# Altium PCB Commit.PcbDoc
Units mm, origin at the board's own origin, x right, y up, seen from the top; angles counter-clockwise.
Board outline 42 x 80 mm, 2 copper layers (Top Layer, Bottom Layer); 82 components, 52 nets, 246 pads, 237 vias.
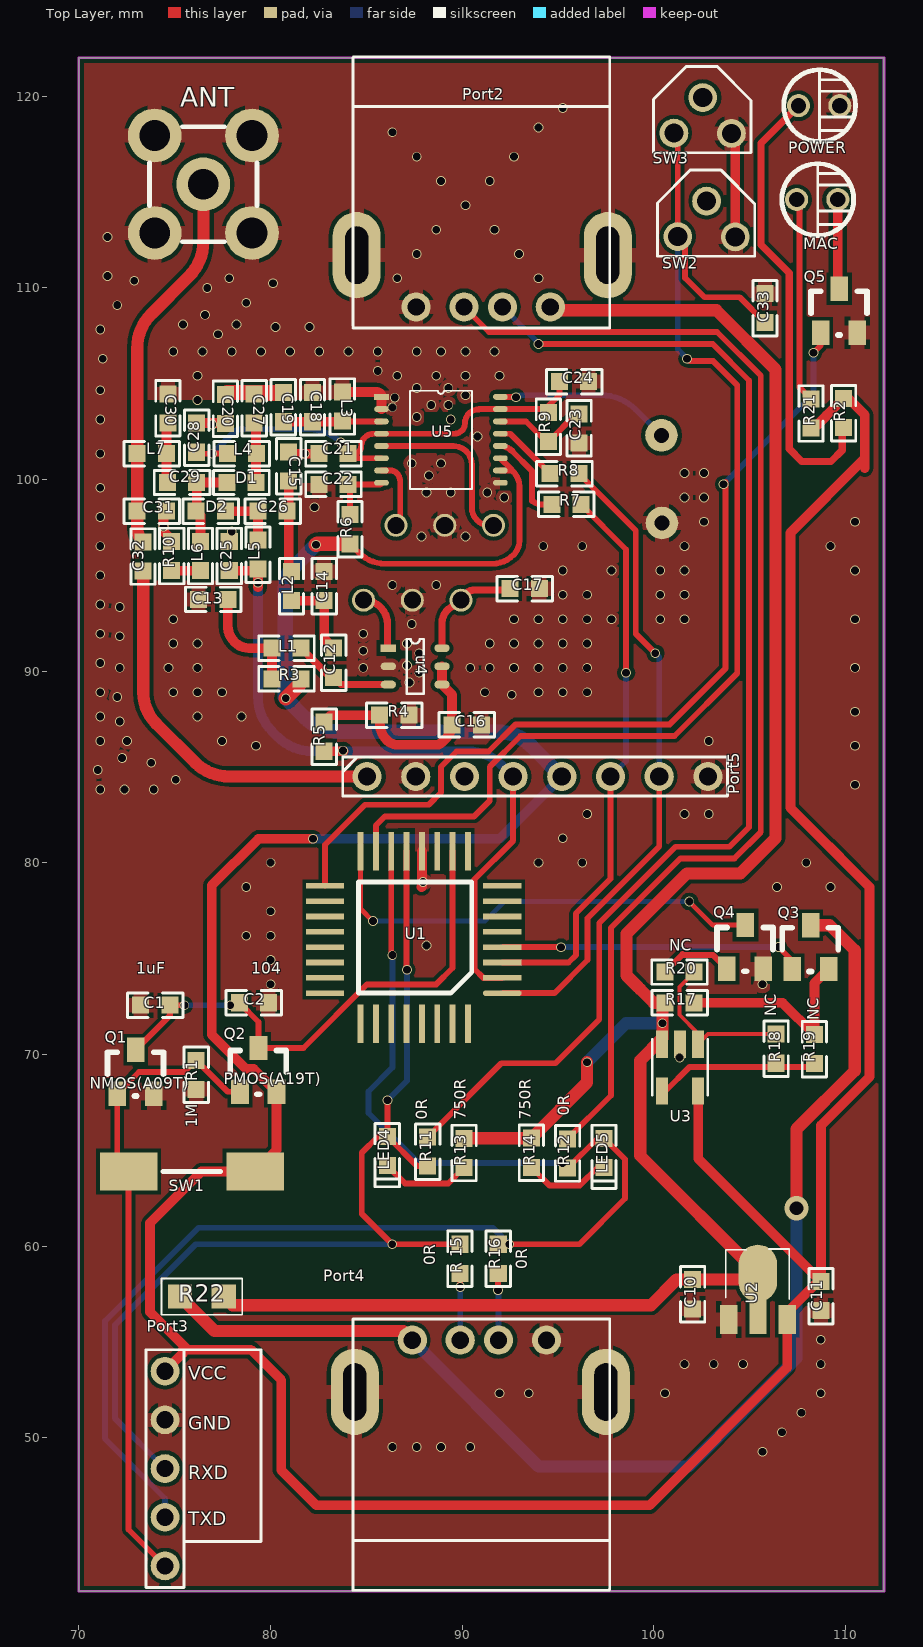
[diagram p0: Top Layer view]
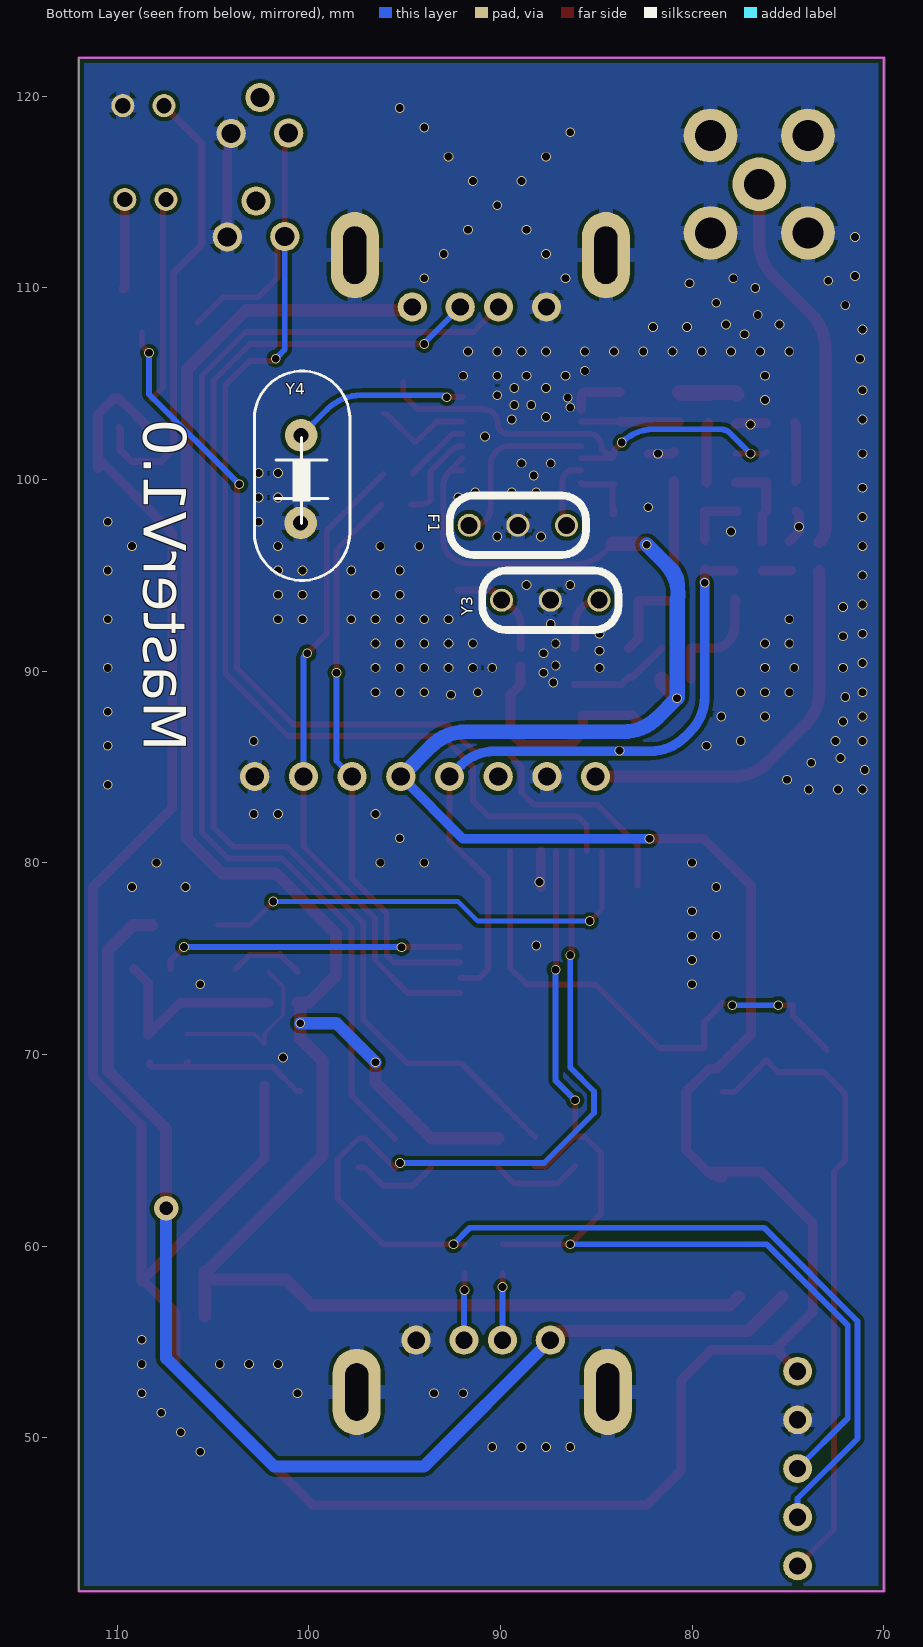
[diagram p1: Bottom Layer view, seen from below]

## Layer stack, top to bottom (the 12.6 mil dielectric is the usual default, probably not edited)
Top Layer: signal copper 0.0356
Dielectric: dielectric 0.32, FR-4, Dk 4.8
Bottom Layer: signal copper 0.0356

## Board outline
70,42 112,42 112,122 70,122

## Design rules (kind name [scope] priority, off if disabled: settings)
Clearance [All] p1: gap=0.203
ComponentClearance [All] p1: gap=0 collisioncheckmode=3 verticalgap=0 showdistances=FALSE
MinimumSolderMaskSliver [All] p1: minsoldermaskwidth=0
PolygonConnect [All] p1: connectstyle=Relief reliefconductorwidth=0.762 reliefentries=4 polygonreliefangle="90 Angle"
RoomDefinition CommitV2.0 [InComponentClass('CommitV2.0')] p1: confinementstyle=ConfineIn formatcopy=TRUE lockcomponents=FALSE outline 0,0 50.8,0 50.8,25.4 0,25.4
RoutingVias [All] p1: holewidth=1.27 width=2.54 viastyle="Through Hole" minholewidth=0.025 minwidth=0.254 maxholewidth=0.711 maxwidth=1.27
SilkToSilkClearance [All] p1: silktosilkclearance=0
SilkscreenOverComponentPads [All] p1: minsilkscreentomaskgap=0
SolderMaskExpansion [All] p1: expansion=0.102
Width [All] p1: maxlimit=0.762 minlimit=0.178 preferedwidth=0.381
24 further rules are at their usual default settings.

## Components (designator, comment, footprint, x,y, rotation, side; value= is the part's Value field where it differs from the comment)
ANT "SMA" SWA-KE天线母座 76.5,115.4 r0 top
C1 "1uF" 0603 73.228,72.572 r0 top
C2 "104" 0603 79.9,72.7 r180 top
C10 "1uF" 0603 102.022,58.258 r270 top
C11 "104" 0603 108.722,58.158 r270 top
C12 "220pF5%" 0603 83.3,91.2 r270 top
C13 "104" 0603 76.25,93.742 r0 top
C14 "4.7pF5%" 0603 82.8,95.2 r270 top
C15 "12pF5%" 0603 80.95,101.442 r270 top
C16 "104" 0603 91,87.2 r180 top
C17 "1pF+-0.25p" 0603 92.5,94.3 r0 top
C18 "NC" 0603 82.194,104.534 r270 top
C19 "1pF+-0.25p" 0603 80.67,104.534 r270 top
C20 "NC" 0603 77.65,104.442 r270 top
C21 "104" 0603 84.05,101.342 r180 top
C22 "104" 0603 84.05,99.742 r180 top
C23 "104" 0603 96.1,101.9 r90 top
C24 "104" 0603 96.6,105.1 r180 top
C25 "NC" 0603 77.85,95.242 r90 top
C26 "NC" 0603 79.35,98.342 r0 top
C27 "NC" 0603 79.15,102.942 r90 top
C28 "104" 0603 76.15,102.942 r270 top
C29 "220pF5%" 0603 76.15,99.842 r180 top
C30 "NC" 0603 74.65,102.942 r90 top
C31 "NC" 0603 73.05,98.342 r0 top
C32 "NC" 0603 73.35,96.742 r270 top
C33 "NC" 0603 105.8,109.7 r270 top
D1 "SMP1320" 0603 79.25,99.842 r180 top
D2 "SMP1320" 0603 77.65,98.342 r180 top
F1 "10.7M" "PT4450 XTAL" 89.093,97.607 r0 bottom
L1 "180nH5%" 0603 81.6,91.2 r180 top
L2 "22nH5%" 0603 81.1,95.2 r270 top
L3 "47nH5%" 0603 83.75,103.042 r90 top
L4 "180nH5%" 0603 77.75,101.342 r0 top
L5 "180nH5%" 0603 79.35,96.842 r270 top
L6 "180nH5%" 0603 76.35,95.242 r90 top
L7 "0R" 0603 73.05,101.342 r0 top
LED4 "RX" LED-0603 86.1,64.2 r90 top
LED5 "TX" LED-0603 97.4,64.1 r90 top
MAC "MAC" 2.54LED 109.8,114.6 r0 top
Port2 "USB_A" USB-A 91.1,109 r180 top
Port3 "DEBUG" STC_DEBUG 74.5,48.4 r0 top
Port4 "USB_B" USB-A 90.9,55.1 r0 top
Port5 "Mold" Pin-8 95.2,84.5 r90 top
POWER "POWER" 2.54LED 109.9,119.5 r0 top
Q1 "NMOS(A09T)" SOT-23 72.9,69.1 r0 top
Q2 "PMOS(A19T)" SOT-23 79.3,69.2 r0 top
Q3 "AO3407(P)" SOT-23 108.1,75.6 r0 top
Q4 "NC" SOT-23 104.7,75.61 r0 top
Q5 "NMOS(A09T)" SOT-23 109.6,108.8 r0 top
R1 "1M" 0603 76.128,68.172 r90 top
R2 "2.2K" 0603 109.9,102.7 r90 top
R3 "0R" 0603 81.6,89.6 r180 top
R4 "100k" 0603 85.7,87.7 r0 top
R5 "0R" 0603 82.8,85.821 r90 top
R6 "10R" 0603 84.15,96.642 r90 top
R7 "10K" 0603 96.2,98.7 r180 top
R8 "10K" 0603 96.1,100.3 r180 top
R9 "5.1M" 0603 94.5,103.5 r270 top
R10 "3.3K" 0603 74.85,95.242 r90 top
R11 "0R" 0603 88.2,65.7 r270 top
R12 "0R" 0603 95.5,65.6 r270 top
R13 "750R" 0603 90.1,64.1 r90 top
R14 "750R" 0603 93.614,64.111 r90 top
R16 "0R" 0603 91.884,58.577 r90 top
R17 "NC" 0603 102.106,72.698 r180 top
R18 "NC" 0603 106.379,69.543 r90 top
R19 "NC" 0603 108.379,71.043 r270 top
R20 "NC" 0603 102.1,74.3 r180 top
R21 "0R" 0603 108.2,104.2 r270 top
R22 "0R" 0805 76.3,57.5 r180 top
"R 15" "0R" 0603 89.884,58.577 r90 top
SW1 "REST" SW-1 77.4,61.9 r270 top
SW2 "REST" Key1 104.2,112.6 r180 top
SW3 "REST" Key1 104,118 r180 top
U1 "STC8F2K32S2" LQPF-32 91.2,72.3 r180 top
U2 "HT7533-1" 3A5A3D 105.43,56.182 r0 top
U3 "NC" AD8628 101.3,69.4 r180 top
u4 "PT4450" PT4450 86.1,91.1 r270 top
U5 "PT4302" PT4302 85.793,104.307 r0 top
Y3 "433.92M" "PT4450 XTAL" 87.4,93.7 r180 bottom
Y4 "13.226M" "PT4306 XTAL" 100.4,102.3 r270 bottom

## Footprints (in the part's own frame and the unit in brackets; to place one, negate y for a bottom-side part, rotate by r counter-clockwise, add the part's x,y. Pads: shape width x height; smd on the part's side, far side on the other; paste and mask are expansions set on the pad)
2.54LED [mm]
  round 1.2 hole 0.8: 1(-2.35,0) 2(-0.2,0)
  silkscreen extent -3.12,-1.87 0.62,1.9
3A5A3D [mm]
  rect 0.9x1.5 smd: 1(-1.524,0) 3(1.524,0)
  rect 0.9x1.8 smd: 2(0,0.15)
  oval 2x3 smd: 2(0,2.4)
  silkscreen extent -1.68,1.07 1.63,3.67
0603 [mil]
  rect 35x35 smd: 1(0,0) 2(60,0)
  silkscreen extent -27,-25 87,25
0805 [mil]
  rect 50x50 smd: 1(-50,5) 2(40,5)
  silkscreen extent -88,-32 78,42
AD8628 [mil]
  rect 24x56 smd: 1(-39.61,-44.88) 2(-2.61,-44.88) 3(34.39,-44.88) 4(34.39,51.12) 5(-39.61,51.12)
  silkscreen extent -60,-55 54,60
Key1 [mm]
  round 1.5 / inner round 1.524 / far side round 1.524 hole 1: 1(2.95,-0.067) 2(-0.05,-0.05) ""(1.45,-1.92)
  silkscreen extent -1.07,-3.55 4.01,0.95
LED-0603 [mil]
  rect 35x35 smd: 1(0,0) 2(60,0)
  silkscreen extent -43,-25 87,25
LQPF-32 [mm]
  oct 2x0.3 smd: 1(-0.9,-0.9)
  rect 2x0.3 smd: 2(-0.9,-1.7) 3(-0.9,-2.5) 4(-0.9,-3.3) 5(-0.9,-4.1) 6(-0.9,-4.9) 7(-0.9,-5.7) 8(-0.9,-6.5) 17(8.35,-6.5) 18(8.35,-5.7) 19(8.35,-4.9) 20(8.35,-4.1) 21(8.35,-3.3) 22(8.35,-2.5) 23(8.35,-1.7) 24(8.35,-0.9)
  rect 0.3x2 smd: 9(0.9,-8.3) 10(1.7,-8.3) 11(2.5,-8.3) 12(3.3,-8.3) 13(4.1,-8.3) 14(4.9,-8.3) 15(5.7,-8.3) 16(6.5,-8.3) 25(6.5,0.7) 26(5.7,0.7) 27(4.9,0.7) 28(4.1,0.7) 29(3.3,0.7) 30(2.5,0.7) 31(1.7,0.7) 32(0.9,0.7)
  silkscreen extent 0.7,-6.7 6.6,-0.9
Pin-8 [mil]
  round 60 hole 37.4: 1(0,400) 2(0,300) 3(0,200) 4(0,100) 5(0,0) 6(0,-100) 7(0,-200) 8(0,-300)
  silkscreen extent -40,-340 40,450
PT4302 [mil]
  rect 30x12 smd: 1(0,0)
  oval 30x12 smd: 2(0,-25.2) 3(0,-50.39) 4(0,-75.59) 5(0,-100.79) 6(0,-125.98) 7(0,-151.18) 8(0,-176.38) 9(244.09,-176.38) 10(244.09,-151.18) 11(244.09,-125.98) 12(244.09,-100.79) 13(244.09,-75.59) 14(244.09,-50.39) 15(244.09,-25.2) 16(244.09,0)
  silkscreen extent 58,-189 186,13
"PT4306 XTAL" [mm]
  round 1.7 hole 0.787: 1(0,0) 2(4.572,-0.025)
  silkscreen extent -3.35,-2.44 7.57,2.54
PT4450 [mm]
  rect 0.4x0.8 smd: 1(-0.1,0.05)
  oval 0.4x0.8 smd: 2(0.85,0.05) 3(1.8,0.05) 4(1.8,2.85) 5(0.85,2.85) 6(-0.1,2.85)
  silkscreen extent -0.57,1 2.28,1.89
"PT4450 XTAL" [mm]
  round 1.2 hole 0.889: 1(-2.54,0) 2(0,0) 3(2.54,0)
  silkscreen extent -3.56,-1.55 3.56,1.55
SOT-23 [mil]
  rect 36x50 smd: 1(40,-45) 2(-35,-45) 3(3,45)
  silkscreen extent -55,-50 60,40
STC_DEBUG [mm]
  round 1.5 hole 0.9: 1(0,5.08) 2(0,2.54) 3(0,0) 4(0,-2.54) 5(0,-5.08)
  silkscreen extent -1,-6.2 5,6.2
SW-1 [mm]
  rect 2x3 smd: 1(-2,1.8) 2(-2,-4.8)
  silkscreen extent -2,-3 -2,0
SWA-KE天线母座 [mm]
  round 2.8 hole 1.6: 1(0,0) 2(-2.54,-2.54) 2(-2.54,2.54) 2(2.54,-2.54) 2(2.54,2.54)
  silkscreen extent -2.8,-3 2.8,3
USB-A [mm]
  round 1.524 hole 0.9: 1(-3.5,0) 2(-1,0) 3(1,0) 4(3.5,0)
  oval 2.5x4.5 hole 1.2 slot 3 at 90 deg: 4(-6.5,-2.7) 4(6.6,-2.7)
  silkscreen extent -6.6,-13.05 6.8,1.1

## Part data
ANT L1 L2 L3 R1 R2 R3 R4 R5 R6 R7 R8 R9 R10 R11 R12 R13 R14 R16 R17 R18 R19 R20 R21 R22 "R 15": library part Res2, "Resistor"
C1 C2 C10 C11 C12 C13 C14 C15 C16 C17 C18 C19 C20 C21 C22 C23 C24 C25 C26 C27 C28 C29 C30 C31 C32 C33: library part Cap, "Capacitor"
D1 D2 LED4 LED5 MAC POWER: library part DIODE, "diode"
F1: library part Filter
L4 L5 L6 L7: library part L, "Inductor"
Port2 Port4: library part USB
Port3: library part PIN-5
Port5: library part Pin-8
Q1 Q5: library part MOSFET-N, "mosfet"
Q2 Q3: library part MOSFET-P, "mosfet"
Q4: library part 2N3904, "NPN General Purpose Amplifier"
SW1 SW2 SW3: library part SW-P, "key"
U1: library part STC8F2K64S2
U3: library part AD8628
Y3: library part PT4450-XTAL
Y4: library part XTAL, "Crystal Oscillator"

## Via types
v1: diameter 0.508, hole 0.406, Top Layer to Bottom Layer, 236 vias
v2: diameter 1.27, hole 0.711, Top Layer to Bottom Layer, 1 vias

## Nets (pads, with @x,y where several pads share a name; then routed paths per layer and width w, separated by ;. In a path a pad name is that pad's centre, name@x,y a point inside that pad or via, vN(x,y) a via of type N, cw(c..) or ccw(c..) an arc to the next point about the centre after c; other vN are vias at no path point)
ANT: ANT.1 C31.1 C32.1 L7.1 | length 19.9
  Top Layer w0.635: C32.1 cw(c74.074,97.466) 73.05,97.466 C31.1 L7.1 73.05,106.84 cw(c75.59,106.84) 73.794,108.637 75.756,110.599 ccw(c73.96,112.395) 76.5,112.395 ANT.1
CEOUT: Q3.2 U1.4 | length 17
  Top Layer w0.305: U1.4 v1(95.158,75.6) ; v1(106.508,75.61) 107.211,74.907 Q3.2
  Bottom Layer w0.305: v1(95.158,75.6) 97.145,75.6 ; 105.664,75.61 105.156,75.61 ; v1(106.508,75.61) 105.156,75.61 ; 97.145,75.6 97.78,75.6 97.79,75.61 ; 97.145,75.6 97.155,75.61 97.79,75.61 ; 97.79,75.61 105.156,75.61
CNET: Q4.3 U1.16 | length 24.3
  Top Layer w0.254: U1.16 84.7,77.606 v1(85.344,76.962) ; v1(101.854,77.978) 103.079,76.753 Q4.3
  Bottom Layer w0.254: v1(85.344,76.962) 91.186,76.962 92.202,77.978 v1(101.854,77.978)
GND: ANT.2 C1.1 C2.1 C10.2 C11.2 C13.1 C14.1 C15.1 C16.1 C17.2 C18.1 C20.2 C21.2 C22.2 C23.1 C24.1 C25.2 C28.1 C30.2 C31.2 C33.1 F1.2 L3.2 Port2.4 Port3.2 Port4.4 Port5.2 Port5.8 POWER.2 Q1.1 Q4.1 Q5.1 R1.1 R4.2 R10.2 SW2.2 SW3.2 U1.12 U2.1 U3.2 u4.2 U5.1 U5.2 U5.9 Y3.2 Y4.2 | length 15
  Top Layer w0.508: C31.2 74.422,98.19 v1(74.422,97.536) 74.422,97.282 R10.2@74.93,96.774 ; C28.1 77.652,102.942 C20.2@77.724,102.87 ; C15.1 81.046,101.346 C21.2@82.296,101.346 ; L3.2 85.534,104.566 cw(c85.534,104.307) U5.1 U5.2 ; 87.884,78.74 ccw(c87.884,78.756) 87.9,78.756 U1.12 ; SW3.2 104.25,117.85 SW2.2
  other v1: 105.664,49.276 86.36,49.53 87.63,49.53 88.9,49.53 90.424,49.53 106.68,50.292 107.696,51.308 91.948,52.324 93.472,52.324 100.584,52.324 108.712,52.324 101.6,53.848 103.124,53.848 104.648,53.848 108.712,53.848 108.712,55.118 101.346,69.85 80.01,73.66 105.664,73.66 80.01,74.93 88.138,75.692 78.74,76.2 80.01,76.2 80.01,77.47 78.74,78.74 106.426,78.74 109.22,78.74 87.96,79 80.01,80.01 93.98,80.01 96.266,80.01 107.95,80.01 95.25,81.28 96.52,82.55 101.6,82.55 102.87,82.55 71.12,83.82 72.39,83.82 73.914,83.82 110.49,84.074 75.057,84.328 70.993,84.836 73.787,85.217 72.263,85.471 79.248,86.106 110.49,86.106 71.12,86.36 72.517,86.36 77.47,86.36 102.87,86.36 72.136,87.376 71.12,87.63 76.2,87.63 78.486,87.63 110.49,87.884 72.009,88.646 92.583,88.773 71.12,88.9 74.93,88.9 76.2,88.9 77.47,88.9 91.186,88.9 93.98,88.9 95.25,88.9 96.52,88.9 87.249,89.408 87.757,89.916 72.136,90.17 74.676,90.17 76.2,90.17 84.836,90.17 90.424,90.17 91.44,90.17 92.71,90.17 93.98,90.17 95.25,90.17 96.52,90.17 110.49,90.17 87.122,90.297 71.12,90.424 87.757,90.932 84.836,91.059 74.93,91.44 76.2,91.44 87.122,91.44 91.44,91.44 92.71,91.44 93.98,91.44 95.25,91.44 96.52,91.44 72.136,91.821 71.12,91.948 84.836,91.948 87.376,92.456 74.93,92.71 92.71,92.71 93.98,92.71 95.25,92.71 96.52,92.71 97.79,92.71 100.33,92.71 101.6,92.71 110.49,92.71 72.136,93.345 71.12,93.472 95.25,93.98 96.52,93.98 100.33,93.98 101.6,93.98 86.36,94.488 88.646,94.488 71.12,94.996 95.25,95.25 97.79,95.25 100.33,95.25 101.6,95.25 110.49,95.25 71.12,96.52 94.234,96.52 96.266,96.52 101.6,96.52 109.22,96.52 87.884,97.028 90.17,97.028 77.978,97.282 102.616,97.79 110.49,97.79 71.12,98.044 82.296,98.552 92.202,99.06 101.6,99.06 102.616,99.06 88.138,99.314 89.408,99.314 91.313,99.314 71.12,99.568 88.265,100.203 101.6,100.33 102.616,100.33 87.376,100.838 88.9,100.838 71.12,101.346 81.788,101.346 90.805,102.235 76.962,102.87 71.12,103.124 89.408,103.124 87.63,103.251 86.36,103.759 88.392,103.886 89.281,103.886 76.2,104.14 86.487,104.267 90.17,104.394 71.12,104.648 87.63,104.775 89.281,104.775 76.2,105.41 86.614,105.41 88.646,105.41 90.17,105.41 91.948,105.41 85.598,105.664 71.247,106.299 74.93,106.68 76.454,106.68 77.978,106.68 79.502,106.68 81.026,106.68 82.55,106.68 84.074,106.68 85.598,106.68 87.63,106.68 88.9,106.68 90.17,106.68 91.694,106.68 77.267,107.569 71.12,107.823 80.264,107.95 82.042,107.95 75.438,108.077 78.232,108.077 76.581,108.585 72.009,109.093 78.74,109.22 76.708,109.982 80.137,110.236 72.898,110.363 77.851,110.49 86.614,110.49 93.98,110.49 71.501,110.617 87.63,111.76 92.964,111.76 71.501,112.649 88.646,113.03 91.694,113.03 90.17,114.3 88.9,115.57 91.44,115.57 87.63,116.84 92.71,116.84 86.36,118.11 93.98,118.364 95.25,119.38
NetC12_1: C12.1 C14.2 L2.2 | length 4.4
  Top Layer w0.508: L2.2 C14.2 82.8,91.7 C12.1
NetC12_2: C12.2 L1.1 u4.3 | length 5.3
  Top Layer w0.381: L1.1 83.124,89.676 C12.2 83.676,89.3 u4.3
NetC13_2: C13.2 L1.2 R3.2 | length 6.1
  Top Layer w0.508: C13.2@77.722,93.616 cw(c77.9,93.616) C13.2 77.774,92.385 ccw(c79.013,92.385) 78.137,91.509 ccw(c78.882,92.254) 78.882,91.2 L1.2 R3.2
NetC16_2: C16.2 R4.1 R5.2 u4.4 u4.5 | length 11.8
  Top Layer w0.508: R5.2 83.155,87.7 R4.1 85.7,87.316 ccw(c87.016,87.316) 86.085,86.386 ccw(c86.646,86.946) 86.646,86.154 88.637,86.154 ccw(c88.637,86.578) 88.937,86.278 89.205,86.546 ccw(c88.551,87.2) C16.2 89.476,88.774 u4.4 u4.5
NetC17_1: C17.1 u4.6 Y3.1 | length 5.8
  Top Layer w0.381: u4.6 88.95,92.506 cw(c89.916,92.506) 89.916,93.472 cw(c90.678,93.472) 90.678,94.234 C17.1@92.202,94.234
  Top Layer w0.762: Y3.1 Y3.1@90.096,93.856
NetC18_2: C18.2 C19.2 L3.1 U5.3 | length 5.2
  Top Layer w0.305: L3.1@83.718,103.01 cw(c83.735,103.01) 83.735,103.027 U5.3
  Top Layer w0.508: C19.2 C18.2 83.718,103.01 L3.1
NetC22_1: C22.1 R6.2 U5.8 | length 5.6
  Top Layer w0.305: U5.8 cw(c85.708,99.827) 85.708,99.742 C22.1 ; R6.2@84.05,98.266 ccw(c84.15,98.266) R6.2 ; R6.2@84.05,98.266 ccw(c84.15,98.266) R6.2 ; R6.2@84.05,98.266 ccw(c84.15,98.266) R6.2 ; R6.2@84.05,98.266 ccw(c84.15,98.266) R6.2 ; C22.1 cw(c84.05,99.642) C22.1@84.15,99.642 ; C22.1 cw(c84.05,99.642) C22.1@84.15,99.642 ; C22.1 cw(c84.05,99.642) C22.1@84.15,99.642 ; C22.1 cw(c84.05,99.642) C22.1@84.15,99.642 ; C22.1 cw(c84.05,99.642) C22.1@84.15,99.642 ; C22.1 cw(c84.05,99.642) C22.1@84.15,99.642 ; C22.1 84.15,99.742 R6.2 ; R6.2 cw(c84.391,98.407) 84.05,98.407 ccw(c84.391,98.407) R6.2
NetC23_2: C23.2 R9.2 U5.14 | length 5.1
  Top Layer w0.305: U5.14 93.326,103.027 94.377,101.976 94.512,101.976 95.96,103.424 C23.2
NetC26_1: C26.1 D2.1 L5.1 | length 3.2
  Top Layer w0.508: D2.1 C26.1 L5.1
NetC27_1: C27.1 D1.1 L4.2 | length 3.1
  Top Layer w0.508: C27.1 79.25,102.842 D1.1
NetC29_1: C29.1 D1.2 D2.2 L6.2 | length 5
  Top Layer w0.381: C29.1@76.126,99.784 cw(c76.208,99.784) C29.1 ccw(c76.208,99.784) C29.1@76.126,99.784
  Top Layer w0.508: L6.2 76.35,98.118 D2.2 ; D1.2 C29.1 76.15,98.366 D2.2 ; D2.2 ccw(c76.068,98.4) 76.15,98.4 cw(c76.068,98.4) D2.2
NetC29_2: C29.2 C30.1 L7.2 | length 5
  Top Layer w0.381: C29.2@74.574,99.968 ccw(c74.751,99.968) C29.2 ; L7.2 ccw(c74.39,101.526) 74.65,101.526 C30.1
  Top Layer w0.508: C29.2@74.574,99.968 L7.2 C30.1@74.574,102.759 ; C30.1@74.574,102.759 cw(c74.833,102.759) C30.1 ccw(c74.833,102.759) C30.1@74.574,102.759
NetC32_2: C32.2 Port5.1 | length 20.3
  Top Layer w0.635: C32.2@73.387,95.128 ccw(c73.26,95.128) C32.2 cw(c73.313,95.181) 73.365,95.181 73.365,88.901 ccw(c75.691,88.901) 74.047,87.256 76.059,85.244 ccw(c77.855,87.04) 77.855,84.5 Port5.1
NetC33_2: C33.2 SW2.1 SW3.1 U1.15 | length 62.2
  Top Layer w0.305: U1.15 85.5,81.944 85.979,82.423 90.627,82.423 91.441,83.237 91.441,85.005 93.05,86.614 101.079,86.614 104.356,89.891 104.356,104.914 103.098,106.172 101.854,106.172 v1(101.727,106.299) ; SW3.1@101.25,117.867 SW2.1 101.633,112.667 101.633,110.508 102.64,109.501 104.475,109.501 C33.2
  Bottom Layer w0.305: SW2.1 101.25,106.776 v1(101.727,106.299)
NetF1_1: F1.1 U5.7 | length 3.7
  Top Layer w0.305: U5.7 86.264,100.467 cw(c86.264,100.024) 86.577,100.337 cw(c86.107,99.867) 86.772,99.867 86.772,98.399 86.772,98.137 cw(c86.023,98.137) F1.1
NetF1_3: F1.3 U5.5 | length 9.2
  Top Layer w0.305: U5.5 89.532,101.747 cw(c89.532,100.771) 90.508,100.771 ccw(c90.508,100.769) 90.506,100.769 90.506,98.524 ccw(c91.423,98.524) 91.423,97.607 F1.3
NetL6_1: L6.1 R10.1 | length 1.5
  Top Layer w0.508: R10.1 L6.1
NetLED4_1: LED4.1 R13.1 | length 4.7
  Top Layer w0.305: LED4.1 87.026,63.274 89.274,63.274 R13.1
NetLED5_1: LED5.1 R14.1 | length 4.6
  Top Layer w0.305: R14.1 94.551,63.174 96.134,63.174 97.06,64.1 LED5.1
NetMAC_1: MAC.1 R21.1 | length 10.7
  Top Layer w0.305: MAC.1 107.607,114.443 107.607,104.793 R21.1
NetMAC_2: MAC.2 Q5.3 | length 5
  Top Layer w0.508: MAC.2@109.376,114.376 MAC.2 109.6,110.019 Q5.3
NetPort2_2: Port2.2 R11.1 | length 64.2
  Top Layer w0.305: R11.1 92.045,69.545 94.869,69.545 97.155,71.831 97.155,76.859 101.132,80.835 103.948,80.835 104.965,81.853 104.965,105.167 103.071,107.061 v1(93.98,107.061)
  Bottom Layer w0.305: Port2.2 93.98,107.12 v1(93.98,107.061)
NetPort2_3: Port2.3 R12.1 | length 62.6
  Top Layer w0.305: Port2.3 91.404,107.696 103.298,107.696 105.575,105.419 105.575,81.601 104.2,80.226 101.384,80.226 97.765,76.606 97.765,67.865 R12.1
NetPort4_2: "R 15.1" Port4.2 | length 3.5
  Top Layer w0.305: 89.884,58.577 89.9,58.561 v1(89.9,57.875)
  Bottom Layer w0.305: Port4.2 v1(89.9,57.875)
NetPort4_3: Port4.3 R16.1 | length 3.5
  Top Layer w0.305: v1(91.872,57.709) 91.872,58.565 R16.1
  Bottom Layer w0.305: v1(91.872,57.709) 91.9,57.681 Port4.3
NetPOWER_1: POWER.1 R2.1 | length 23.8
  Top Layer w0.381: POWER.1 105.588,117.538 105.588,112.243 107.061,110.769 107.061,101.6 107.721,100.94 109.245,100.94 109.83,101.524 109.83,102.63 R2.1
NetQ3_1: Q3.1 R17.1 R19.1 | length 10.7
  Top Layer w0.508: R17.1 106.724,72.698 R19.1 108.379,73.72 Q3.1
NetQ4_2: Q4.2 R20.2 | length 5.2
  Top Layer w0.305: 101.499,75.235 100.576,74.312 R20.2 101.46,75.184 103.094,75.184 Q4.2
NetQ5_2: Q5.2 U1.17 | length 47.5
  Top Layer w0.305: U1.17 82.85,80.945 84.938,83.033 88.265,83.033 88.901,83.668 88.901,85.005 89.701,85.805 91.379,85.805 92.797,87.224 100.827,87.224 103.746,90.143 103.746,99.86 v1(103.632,99.746) ; v1(108.331,106.604) 108.411,106.684 108.711,106.984 Q5.2
  Bottom Layer w0.305: v1(103.632,99.746) 108.331,104.445 v1(108.331,106.604)
NetR7_2: R7.2 U5.12 | length 5.5
  Top Layer w0.305: 92.619,101.488 ccw(c91.993,100.861) U5.12 cw(c91.993,100.984) 92.532,101.524 cw(c92.532,101.462) 92.576,101.506 93.624,100.457 cw(c93.563,100.396) 93.65,100.396 93.65,98.882 93.675,98.882 ccw(c94.115,99.322) 94.115,98.7 R7.2 R7.2@94.64,98.7
NetR8_2: R8.2 U5.13 | length 3.5
  Top Layer w0.305: U5.13 92.507,102.387 94.576,100.318 R8.2
NetR18_1: R18.1 R19.2 U3.4 | length 8.8
  Top Layer w0.305: U3.4 100.614,68.102 101.854,69.342 108.202,69.342 R19.2 R19.2@108.276,69.621 ; R18.1@106.3,69.621 R18.1
NetR18_2: R18.2 R20.1 U3.1 | length 8.8
  Top Layer w0.203: R20.1 101.332,73.532 101.332,72.074 102.306,71.1 U3.1 102.833,71.067 R18.2
Netu4_1: u4.1 Y3.3 | length 9.9
  Top Layer w0.381: u4.1@86.106,91.186 u4.1@86.106,91.244 ; Y3.3 cw(c84.86,92.454) 86.106,92.454 ; Y3.3 cw(c84.86,92.454) 86.106,92.454 ; Y3.3 cw(c84.86,92.454) 86.106,92.454 ; Y3.3 cw(c84.86,92.454) 86.106,92.454 ; u4.1@86.106,91.244 ccw(c86.15,91.244) u4.1 ; u4.1@86.106,91.244 ccw(c86.15,91.244) u4.1 ; u4.1@86.106,91.244 ccw(c86.15,91.244) u4.1 ; u4.1@86.106,91.244 ccw(c86.15,91.244) u4.1 ; u4.1@86.106,91.244 ccw(c86.15,91.244) u4.1 ; u4.1@86.106,91.244 ccw(c86.15,91.244) u4.1 ; u4.1@86.106,91.244 ccw(c86.15,91.244) u4.1 ; u4.1@86.106,91.244 ccw(c86.15,91.244) u4.1 ; u4.1@86.106,91.244 ccw(c86.15,91.244) u4.1 ; u4.1@86.106,91.244 ccw(c86.15,91.244) u4.1 ; u4.1@86.106,91.244 86.106,92.454
  Top Layer w0.762: Y3.3 Y3.3@84.956,93.604
NetU5_16: U5.16 Y4.1 | length 9.3
  Top Layer w0.305: U5.16 v1@92.809,104.307 ; v1(92.806,104.292) cw(c92.849,104.292) v1@92.809,104.307 ; v1@92.809,104.307 cw(c92.849,104.292) 92.849,104.335 cw(c92.821,104.335) 92.821,104.307 v1@92.809,104.307
  Bottom Layer w0.305: v1(92.806,104.292) v1@92.964,104.292 ; v1@92.964,104.394 97.254,104.394 cw(c97.254,101.854) 99.05,103.65 Y4.1
RFRXD: Port5.7 R8.1 U1.1 | length 33.8
  Top Layer w0.305: U1.1 94.815,73.2 96.545,74.93 96.545,77.111 100.28,80.846 Port5.7 ; R8.1 99.06,97.34 99.06,91.948 v1(100.076,90.932)
  Bottom Layer w0.305: v1(100.076,90.932) 100.28,90.728 Port5.7
RFTXD: C25.1 L5.2 Port5.4 R5.1 U1.2 | length 36.8
  Top Layer w0.305: U1.2 91.103,74 90.643,74.461 90.643,79.139 92.66,81.157 Port5.4
  Top Layer w0.508: C25.1 78.644,95.242 79.274,95.242 L5.2 79.35,94.386 cw(c79.334,94.386) 79.345,94.375 v1(79.345,94.614) ; R5.1 83.82,85.821 v1(83.789,85.852)
  Bottom Layer w0.508: v1@79.353,94.632 ccw(c79.372,94.614) v1(79.345,94.614) 79.345,88.655 ccw(c81.885,88.655) 80.089,86.859 80.378,86.57 ccw(c82.174,88.366) 82.174,85.826 ccw(c82.187,85.839) 82.187,85.821 82.804,85.821 90.313,85.821 cw(c90.313,83.343) 92.065,85.095
RX: C19.1 C20.1 C27.2 | length 4.7
  Top Layer w0.762: C20.1@77.708,104.466 ccw(c77.708,104.384) C20.1 77.742,104.534 C19.1 80.602,104.466 C27.2
RXCE: Port5.6 R7.1 U1.3 | length 29.7
  Top Layer w0.305: U1.3 95.553,74.8 95.936,75.183 95.936,77.364 97.111,78.539 97.74,79.168 Port5.6 Port5.6@97.652,84.412 ; R7.1 98.552,96.348 v1(98.552,89.916)
  Bottom Layer w0.305: Port5.6 98.552,85.312 98.552,87.376 v1(98.552,89.916)
RXD: "R 15.2" LED4.2 Port3.3 R11.2 U1.13 | length 53.5
  Top Layer w0.305: v1(86.106,67.615) 86.1,67.609 LED4.2 ; U1.13 87.1,74.444 v1(87.122,74.422) ; R11.2 87.66,64.176 86.112,65.724 LED4.2 ; 89.884,60.101 v1(86.355,60.101) 84.76,61.697 84.76,64.872 85.612,65.724 LED4.2
  Bottom Layer w0.305: Port3.3 71.882,51.018 71.882,55.879 76.104,60.101 v1(86.355,60.101) ; v1(86.106,67.615) 87.122,68.631 v1(87.122,74.422)
TRG: Port3.5 Q1.2 Q2.2 R1.2 SW1.2 | length 33.5
  Top Layer w0.305: Port3.5 72.6,45.22 SW1.2 72.011,64.489 Q1.2 73.142,69.088 75.52,69.088 R1.2 77.767,68.057 Q2.2
TX: C15.2 C26.2 L2.1 | length 4.8
  Top Layer w0.508: C15.2 80.95,95.35 L2.1
TXD: LED5.2 Port3.4 R12.2 R16.2 U1.14 | length 74.5
  Top Layer w0.305: U1.14 86.3,75.244 v1(86.36,75.184) ; R16.2 96.118,60.101 98.501,62.484 98.501,64.534 97.412,65.624 LED5.2 97.06,65.624 95.512,64.076 R12.2 v1(95.238,64.338)
  Bottom Layer w0.305: Port3.4 74.5,46.836 71.374,49.962 71.374,56.089 76.245,60.96 91.597,60.96 v1(92.456,60.101) ; v1(86.36,75.184) 86.36,69.317 85.115,68.072 85.115,66.954 87.732,64.338 v1(95.238,64.338)
V2: C21.1 C24.2 C28.2 L4.1 R9.1 U5.4 U5.6 U5.15 | length 34.4
  Top Layer w0.305: C28.2 76.226,101.342 L4.1 77.746,101.346 v1(76.962,101.346) ; v1(83.669,101.929) 84.05,101.548 C21.1 ; U5.6 84.852,101.107 84.285,101.107 cw(c84.285,101.342) C21.1 ; C24.2 95.076,104.41 94.333,103.667 U5.15 90.879,103.667 ccw(c90.879,103.657) 90.869,103.657 ccw(c90.869,102.932) 90.145,102.932 90.145,102.924 cw(c89.607,102.924) 89.607,102.387 U5.4 85.385,102.387 ccw(c85.385,101.738) 84.736,101.738 cw(c84.34,101.738) 84.34,101.342 C21.1
  Bottom Layer w0.305: v1@77.064,101.346 v1(76.962,101.346) 78.052,102.436 cw(c78.486,102.003) 78.486,102.616 82.01,102.616 ; 78.994,102.616 82.01,102.616 ; 82.01,102.616 cw(c82.01,100.27) v1(83.669,101.929) ; 82.01,102.616 cw(c82.01,100.27) v1(83.669,101.929) ; 82.01,102.616 cw(c82.01,100.27) v1(83.669,101.929) ; 82.01,102.616 cw(c82.01,100.27) v1(83.669,101.929)
VCC: C11.1 Port3.1 Port5.5 Q2.1 R2.2 R3.1 R6.1 R21.2 SW1.1 U2.3 U3.5 U5.10 U5.11 | length 219.9
  Top Layer w0.305: R6.1 84.626,96.166 ccw(c85.979,97.519) 85.979,95.606 91.581,95.606 ccw(c91.581,97.167) 92.685,96.063 ccw(c91.949,96.799) 92.989,96.799 92.989,99.645 ccw(c91.949,99.645) 92.685,100.381 ccw(c92.476,100.173) 92.476,100.467 U5.10 U5.10@92.126,100.467 ; U5.11 92.583,100.517 92.583,100.457
  Top Layer w0.508: Port3.1 75.438,54.418 75.438,54.61 ; SW1.1@78.418,63.576 ccw(c78.418,64.682) SW1.1 ; v1(82.22,81.255) 79.375,81.255 76.937,78.816 76.937,71.044 78.73,69.251 79.122,69.251 Q2.1 80.316,65.016 SW1.1 ; U3.5@102.312,68.4 102.312,64.568 C11.1 ; R21.2@108.209,102.667 108.343,102.667 108.998,103.322 108.998,103.334 109.888,104.224 R2.2 110.152,104.224 110.998,103.378 110.998,101.092 ; 109.728,80.264 108.458,81.534 ; 110.998,100.584 110.998,101.092 ; SW1.1 76.397,63.9 73.711,61.214 73.711,56.566 75.677,54.6 78.979,54.6 80.569,53.01 80.569,48.311 82.398,46.482 99.771,46.482 106.954,53.665 U2.3 106.954,56.546 108.567,58.158 C11.1 ; 108.458,81.534 107.124,82.867 107.124,97.218 110.998,101.092 ; 108.458,81.534 111.252,78.74 111.252,68.834 108.722,66.304 C11.1
  Top Layer w0.762: v1@80.793,88.584 cw(c80.796,88.584) v1(80.794,88.586) 81.453,89.246 ccw(c81.099,89.6) R3.1 ; v1(82.374,96.597) cw(c82.483,96.488) 82.483,96.642 R6.1
  Bottom Layer w0.508: v1(82.22,81.255) 91.955,81.255 Port5.5
  Bottom Layer w0.762: v1@80.823,88.656 cw(c80.724,88.656) v1@80.794,88.586 ; Port5.5 93.607,86.093 ccw(c91.811,84.297) 91.811,86.837 83.595,86.837 cw(c83.595,89.377) 81.799,87.581 v1(80.794,88.586) ; 80.748,93.861 cw(c80.546,93.716) 80.794,93.716 v1@80.794,88.586 ; 80.748,93.861 ccw(c80.546,93.716) 80.721,93.892 cw(c83.261,93.892) 80.748,94.256 ; 80.748,93.861 80.748,94.256 ; 80.748,93.861 80.748,88.698 ccw(c80.905,88.698) v1(80.794,88.586) ; 80.748,94.256 cw(c83.261,93.892) 81.465,95.688 v1(82.374,96.597) 81.075,95.298 ccw(c81.829,94.543) 80.763,94.543 80.763,94.354 cw(c80.712,94.354) 80.748,94.318 80.748,94.256
VCC_5V: C10.1 Port2.1 R13.2 R14.2 R17.2 R22.1 U2.2 U3.3 | length 113.8
  Top Layer w0.635: R22.1 78.022,56.921 99.847,56.921 101.184,58.258 105.106,58.258 105.43,58.582 99.289,64.723 99.289,69.694 100.433,70.838 100.445,70.851 R17.2@100.445,72.561 ; R13.2 90.111,65.635 R14.2 96.52,68.541 v1(96.52,69.596) ; Port2.1 94.772,108.828 103.262,108.828 106.35,105.74 106.35,81.28 104.521,79.451 101.727,79.451 98.577,76.302 98.577,74.117 99.2,73.494 ; 99.289,73.406 99.997,72.698 R17.2 R17.2@100.445,72.561 ; R17.2@100.433,72.548 R17.2@100.445,72.561 ; U2.2@105.43,56.332 U2.2@105.43,58.68
  Bottom Layer w0.635: v1(96.52,69.596) 98.552,71.628 v1(100.445,71.628)
VCORE: C1.2 C2.2 Q1.3 Q2.3 U1.10 | length 27
  Top Layer w0.305: Q1.3 74.752,72.019 C1.2 v1(75.51,72.572) ; v1(77.906,72.572) C2.2@77.978,72.644 ; C2.2 79.376,71.7 Q2.3 81.722,70.343 85.039,73.66 88.646,73.66 89.5,74.514 89.5,78.74 U1.10
  Bottom Layer w0.305: v1(75.51,72.572) v1(77.906,72.572)
VOUT: Port4.1 Q3.3 R22.2 | length 63.5
  Top Layer w0.635: R22.2 77.082,55.575 86.925,55.575 Port4.1 ; v2(107.442,61.976) 107.442,66.12 110.477,69.155 110.477,75.438 109.172,76.743 Q3.3
  Bottom Layer w0.635: Port4.1 93.986,48.514 98.044,48.514 101.803,48.514 107.442,54.153 v2(107.442,61.976)
pads on no net: Port5.3 SW2. SW3. U1.5 U1.6 U1.7 U1.8 U1.9 U1.11 U1.18 U1.19 U1.20 U1.21 U1.22 U1.23 U1.24 U1.25 U1.26 U1.27 U1.28 U1.29 U1.30 U1.31 U1.32

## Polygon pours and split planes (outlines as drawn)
GND on Top Layer "Top Layer-No Net" (solid, remove dead copper, pour order 1000): 67.31,126.492 66.802,125.984 66.802,39.116 127.508,39.116 130.048,36.576 121.412,45.212 121.412,128.524
GND on Bottom Layer "Top Layer-No Net" (solid, remove dead copper, pour order 1000): 65.786,129.286 cw(c65.173,128.673) 66.04,128.673 66.04,40.132 132.806,40.132 cw(c132.806,37.592) 134.602,39.388 135.89,38.1 117.076,56.914 cw(c118.872,58.71) 116.332,58.71 116.332,128.016

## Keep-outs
Keep-Out Layer:
  the board outline again, w0.152

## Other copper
Top Layer:
  pour cut-out: 84.836,104.14 73.152,104.14 73.152,94.742 80.772,94.742 80.518,94.996 80.518,99.822 84.836,99.822

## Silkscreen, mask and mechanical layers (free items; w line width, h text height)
Bottom Overlay:
  text "MasterV1.0" at 109.342,85.797 h3.81 r90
